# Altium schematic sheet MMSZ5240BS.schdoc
size 127 x 101 mm
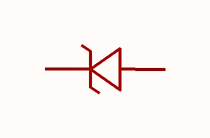
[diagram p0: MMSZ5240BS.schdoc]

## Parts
U?  mmsz5240bs  [SOD-323_L1.7-W1.3-LS2.5-RD]  (value not drawn)

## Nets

Not connected (* = marked no-connect by the designer): U? 1(K) 2(A)

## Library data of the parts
U? = mmsz5240bs: 二极管配置:1个独立式;稳压值(标称值):10V;稳压值(范围):9.5V~10.5V;耗散功率(Pd):200mW;; Manufacturer: CJ(江苏长电/长晶); AddInBom: yes; ModelId: 0f2f330c645944df9245ac3c3fec3456; ModelName: SOD-323_L1.7-W1.3-LS2.5-FD; ModelTransform: 98.425,49.2125,0,0,0,0,0,0,0; Diode Configuration: 1个独立式; Zener Voltage(Nom): 10V; Reverse Leakage Current (Ir): 3uA; Pd - Power Dissipation: 200mW; Impedance(Zzt): 17Ω; Impedance(Zzk): 600Ω; Operating Junction Temperature Range: -55℃~+150℃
